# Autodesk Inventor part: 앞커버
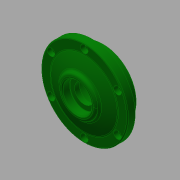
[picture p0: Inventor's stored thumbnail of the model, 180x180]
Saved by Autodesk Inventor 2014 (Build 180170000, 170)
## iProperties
Created: 2016-05
Part Number: 앞커버
Document SubType Name: Modeling
Designer: mduedu
Density: 2.71 g/cm^3
Material: 알루미늄 6061
Appearance: 진녹색
Author: mduedu
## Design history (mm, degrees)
sketch "스케치1"
  geometry: C1 r 35 at (0, 0); C2 r 45 at (0, 0); 1 further point
  constraints: 2 centre point, 2 coincident
  dimensions: "d33" = 90 diameter of C2; "d34" = 70 diameter of C1
extrude "돌출1" new body sketch "스케치1" distance "d0" = 8; taper "d1" = 0 deg
extrude "돌출2" join sketch "스케치1" distance "d2" = 8; taper "d3" = 0 deg; dims "d35" = 12, "d36" = 0
sketch "스케치5"
  geometry: L1 (-45, 8)-(45, 8) reference; L2 (0, 0)-(0, 15); L3 (-45, 0)-(45, 0) reference; L4 (35, 8)-(0, 8); A1 r 91 centre (0, -76) between (35, 8) and (0, 15)
  constraints: 4 end point, 3 point on line, 2 point on circle, 1 centre point, 1 midpoint, 1 perpendicular
  dimensions: "d37" = 35 distance from line of L2 L4.start; "d39" = 7 distance from line of L1 L2.end
revolve "회전2" sketch "스케치5" stored, may be unused: angle "d40" = 90 deg
node "작업 평면1"
sketch "스케치6"
  geometry: C1 r 20 at (0, 0); 1 further point
  constraints: 1 centre point, 1 coincident
  dimensions: "d42" = 40 diameter of C1
extrude "돌출4" join sketch "스케치6" stored distance "d43" = 10; taper "d44" = 0 deg
sketch "스케치4"
  geometry: L1 (0, -12)-(0, 16); L2 (-20, -12)-(-20, 0); L3 (-20, 0)-(-15, 0); L4 (-15, 0)-(-15, 3); L5 (-15, 3)-(-10, 3); L6 (-10, 3)-(-10, 8); L7 (-10, 8)-(-15, 8); L8 (-15, 8)-(-15, 16); L9 (35, -12)-(-35, -12) reference; L10 (-20, 16)-(20, 16) reference; 1 further point
  constraints: 16 end point, 6 parallel, 3 point on line, 2 midpoint, 1 perpendicular, 1 vertical
  dimensions: "d15" = 40 diameter of L2 L1; "d16" = 30 diameter of L8 L1; "d18" = 12 distance of L2.start L2.end; "d19" = 3 distance of L3.end L4.end; "d20" = 30 diameter of L4 L1; "d21" = 20 diameter of L6 L1; "d45" = 8 distance of L7.end L8.end
revolve "회전1" sketch "스케치4" stored, may be unused: angle "d22" = 90 deg
fillet "모깎기2" dims "d23" = 3
fillet "모깎기3" dims "d24" = 0.3
chamfer "모따기2" distance "d46" = 1; stored, may be unused: second distance "d47" = 2, angle "d48" = 45 deg
fillet "모깎기4" dims "d49" = 3
fillet "모깎기5" dims "d50" = 3
fillet "모깎기6" dims "d51" = 1
sketch "스케치7" dims "d52" = 80
  geometry: C1 r 35.595 at (0, 0) reference; C2 r 44 at (0, 0) reference; 7 further points
  constraints: 2 vertical alignment, 1 coincident, 9 other
  dimensions: "d55" = 360 deg dimension on C1.centre point (0, 40) (derived)
sketch "스케치8"
  geometry: 6 further points
  constraints: 6 other
hole "구멍2" sketch "스케치8" at (-34.641, 20), (-34.641, -20), (0, -40), (34.641, -20), (34.641, 20), (0, 40) diameter "d57" = 4.5; stored, may be unused: countersink angle "d61" = 90 deg, drill point angle "d63" = 0 deg; dims "d58" = 6, "d59" = 8, "d60" = 4.6, "d62" = 8
node "솔리드1"
other parameters: "d41" = 8
